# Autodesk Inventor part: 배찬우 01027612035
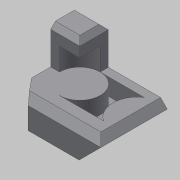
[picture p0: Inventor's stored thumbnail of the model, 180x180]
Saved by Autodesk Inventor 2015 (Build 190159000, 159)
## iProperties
Created: 2015-03
Part Number: 배찬우 01027612035
Material: 일반
Document SubType Name: Modeling
Designer: Deny
Density: 1 g/cm^3
Appearance: 기본값
Author: Deny
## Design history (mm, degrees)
sketch "스케치1"
  geometry: L1 (-43, -56)-(87, -56); L2 (87, -56)-(87, 42); L3 (87, 42)-(-43, 42); L4 (-43, 42)-(-43, -56); 1 further point
  constraints: 8 end point, 2 parallel, 1 horizontal, 1 perpendicular
  dimensions: "d0" = 43 distance from line of point (0, 0) L4; "d1" = 42 distance from line of point (0, 0) L3; "d2" = 98 distance of L1.end L2.end; "d3" = 130 distance of L1.start L1.end
extrude "돌출1" new body sketch "스케치1" distance "d4" = 42; taper "d5" = 0 deg
sketch "스케치2"
  geometry: L1 (0, 0)-(-43, 0); L2 (-43, 0)-(-43, 42); L3 (-43, 42)-(0, 42); L4 (0, 42)-(0, 0)
  constraints: 8 end point, 2 parallel, 1 horizontal, 1 perpendicular
extrude "돌출2" join sketch "스케치2" distance "d6" = 55; taper "d7" = 0 deg
sketch "스케치3"
  geometry: L1 (-43, 0)-(-43, -56) reference; L2 (-43, -56)-(87, -56) reference; L3 (0, 30)-(65, 30); L4 (0, -30)-(65, -30); L5 (0, 0)-(84.9, 0); L6 (-43, -28)-(-20, -56); A1 r 30 centre (0, 0) between (0, 30) and (0, -30); A2 r 36 centre (84.9, 0) between (65, 30) and (65, -30); 1 further point
  constraints: 8 end point, 4 point on circle, 3 horizontal, 2 centre point, 2 tangent, 1 coincident, 1 midpoint, 1 point on line
  dimensions: "d8" = 65 distance of L3.start L3.end; "d9" = 30 radius of A1; "d10" = 36 radius of A2; "d11" = 28 distance from line of L2 L6.start; "d12" = 23 distance from line of L1 L6.end
extrude "돌출3" cut sketch "스케치3" stored distance "d13" = 55; taper "d14" = 0 deg
extrude "돌출4" cut sketch "스케치3" distance "d15" = 33; taper "d16" = 0 deg
extrude "돌출5" cut sketch "스케치3" distance "d17" = 25; taper "d18" = 0 deg
sketch "스케치4"
  geometry: C1 r 25 at (0, 0); 1 further point
  constraints: 1 centre point, 1 coincident
  dimensions: "d19" = 50 diameter of C1
extrude "돌출6" cut sketch "스케치4" distance "d20" = 25; taper "d21" = 0 deg
chamfer "모따기1" distance "d22" = 10; stored, may be unused: second distance "d23" = 2, angle "d24" = 45 deg
chamfer "모따기2" distance "d25" = 7; stored, may be unused: second distance "d26" = 2, angle "d27" = 45 deg
sketch "스케치5"
  geometry: L1 (0, 0)-(107, 0) reference; L2 (107, 0)-(107, 32) reference; L3 (107, 32)-(75, 0); 1 further point
  constraints: 2 end point, 1 point on line
  dimensions: "d28" = 45 deg angle of L1 L3
extrude "돌출7" cut sketch "스케치5" stored distance "d29" = 25; taper "d30" = 0 deg
node "솔리드1"
